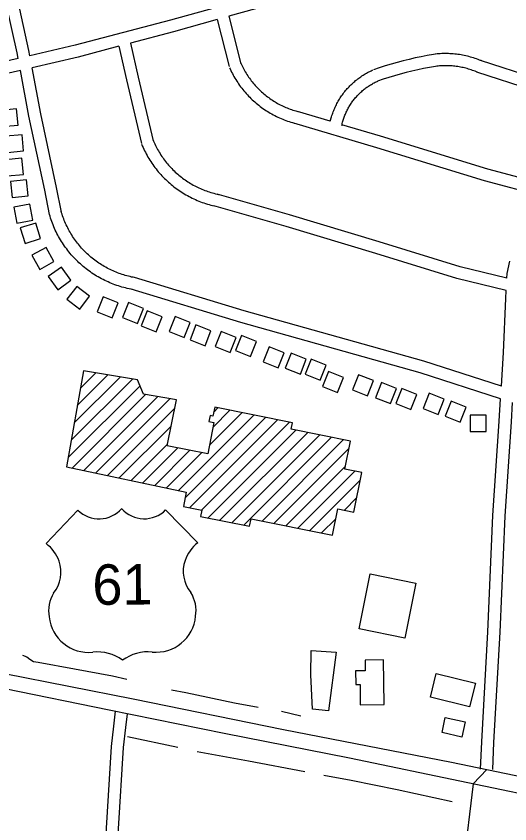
# Model space of a CAD drawing. Extents: x 3540316 to 3578335, y 553172 to 578787.
# Drawn here: x 3544439 to 3545660, y 572760 to 574758 of the extents above; entities that cross this region are included whole.
import ezdxf

# ---------------------------------------------------------------- set-up
doc = ezdxf.new("R2010")
doc.units = 0
for name, color, linetype in [('V-BLDG-OTLN', 7, 'Continuous'), ('V-ROAD-CNTR', 7, 'Continuous'), ('V-ROAD-IDEN', 7, 'Continuous'), ('V-TOPO-SHOR', 7, 'Continuous')]:
    doc.layers.add(name, color=color, linetype=linetype)

msp = doc.modelspace()

# ---------------------------------------------------------------- linework, layer by layer
at = {"layer": 'V-BLDG-OTLN'}
for p, q in [((3544583, 573752), (3544696.6, 573865.7)), ((3544590.5, 573794.9), (3544666.2, 573870.7)), ((3544598, 573837.8), (3544635.9, 573875.7)), ((3544567.9, 573666.3), (3544745.6, 573844)), ((3544575.5, 573709.2), (3544726.9, 573860.7)), ((3544577.5, 573640.5), (3544759.3, 573822.3)), ((3544606.7, 573634.4), (3544789.7, 573817.3)), ((3544636, 573628.3), (3544820, 573812.3)), ((3544665.2, 573622.1), (3544831.9, 573788.8)), ((3544926.2, 573741.7), (3544967.9, 573783.4)), ((3544927.8, 573778.7), (3544938.4, 573789.3)), ((3544840.5, 573585.3), (3545026.8, 573771.6)), ((3544857.1, 573566.6), (3545056.2, 573765.7)), ((3544917.3, 573697.5), (3544997.3, 573777.5)), ((3544918.9, 573769.8), (3544919.2, 573770.1)), ((3544694.4, 573616), (3544822.5, 573744.1)), ((3544868.5, 573542.6), (3545085.7, 573759.8)), ((3544898, 573536.7), (3545115.1, 573753.9)), ((3544913.8, 573517.2), (3545131.2, 573734.5)), ((3544943.3, 573511.3), (3545160.6, 573728.6)), ((3544972.7, 573505.4), (3545190.1, 573722.7)), ((3545002.2, 573499.5), (3545219.5, 573716.8)), ((3545047.5, 573509.4), (3545249, 573710.9)), ((3544723.6, 573609.9), (3544813.2, 573699.4)), ((3544752.9, 573603.7), (3544839.5, 573690.4)), ((3544782.1, 573597.6), (3544869, 573684.5)), ((3545076.9, 573503.5), (3545262.7, 573689.3)), ((3544811.3, 573591.5), (3544898.4, 573678.6)), ((3545106.4, 573497.6), (3545253.8, 573645.1)), ((3545135.8, 573491.7), (3545276.9, 573632.8)), ((3545165.3, 573485.8), (3545290.1, 573610.7)), ((3545251.2, 573536.4), (3545281.3, 573566.5)), ((3545194.7, 573479.9), (3545229.6, 573514.8))]:
    msp.add_line(p, q, dxfattribs=at)
for points in [[(3544404.1, 574485), (3544443.9, 574489), (3544440, 574528.8), (3544400.2, 574524.8)], [(3544418, 574421.4), (3544457.8, 574425.3), (3544453.8, 574465.1), (3544414, 574461.2)], [(3544417.3, 574363), (3544457.1, 574366.9), (3544453.1, 574406.7), (3544413.3, 574402.8)], [(3544429, 574309.9), (3544468.8, 574313.9), (3544464.9, 574353.7), (3544425.1, 574349.7)], [(3544480.6, 574253.6), (3544473.2, 574292.9), (3544433.9, 574285.6), (3544441.3, 574246.3)], [(3544499.5, 574208), (3544487.7, 574246.2), (3544449.5, 574234.4), (3544461.3, 574196.2)], [(3544532.5, 574151.3), (3544513.2, 574186.3), (3544478.2, 574167), (3544497.5, 574132)], [(3544574.5, 574105.1), (3544551.1, 574137.5), (3544518.7, 574114.1), (3544542.1, 574081.7)], [(3544620.9, 574065.4), (3544589.2, 574089.8), (3544564.8, 574058.1), (3544596.5, 574033.7)], [(3544691.5, 574049.6), (3544654.4, 574064.3), (3544639.6, 574027.2), (3544676.8, 574012.4)], [(3544753.9, 574035.1), (3544716.8, 574049.9), (3544702, 574012.7), (3544739.2, 573997.9)], [(3544800.5, 574014.7), (3544763.3, 574029.5), (3544748.5, 573992.3), (3544785.7, 573977.5)], [(3544869.8, 574000.4), (3544832.6, 574015.1), (3544817.9, 573978), (3544855, 573963.2)], [(3544921.1, 573980.3), (3544884, 573995.1), (3544869.2, 573957.9), (3544906.4, 573943.2)], [(3544983.3, 573963.4), (3544946.1, 573978.2), (3544931.4, 573941), (3544968.5, 573926.3)], [(3545033.6, 573953.3), (3544996.5, 573968), (3544981.7, 573930.9), (3545018.9, 573916.1)], [(3545101.9, 573925.3), (3545064.7, 573940.1), (3545050, 573902.9), (3545087.1, 573888.1)], [(3545156.9, 573909.6), (3545119.7, 573924.4), (3545104.9, 573887.2), (3545142.1, 573872.4)], [(3545206, 573895.1), (3545168.8, 573909.9), (3545154, 573872.7), (3545191.2, 573858)], [(3544605.5, 573880.7), (3544563.9, 573643.4), (3544860.1, 573581.2), (3544852.9, 573545.8), (3544898.4, 573536.7), (3544895.3, 573520.9), (3545016.6, 573496.6), (3545020.3, 573514.9), (3545221.5, 573474.5), (3545234.6, 573539.7), (3545274.3, 573531.8), (3545293.9, 573629.4), (3545252.4, 573637.8), (3545266.3, 573707.4), (3545119.3, 573736.9), (3545122.4, 573752.4), (3544930.3, 573790.9), (3544925.8, 573768.8), (3544919, 573770.2), (3544916.1, 573756), (3544928.5, 573753.5), (3544912.9, 573675.7), (3544812.4, 573695.8), (3544836.2, 573809.6), (3544754.4, 573823.1), (3544739.5, 573858.6)], [(3545249, 573864.3), (3545211.8, 573879), (3545197, 573841.9), (3545234.2, 573827.1)], [(3545323, 573856.7), (3545285.8, 573871.5), (3545271, 573834.3), (3545308.2, 573819.5)], [(3545379.9, 573837), (3545342.7, 573851.8), (3545327.9, 573814.6), (3545365.1, 573799.9)], [(3545430, 573822.8), (3545392.8, 573837.6), (3545378.1, 573800.4), (3545415.2, 573785.7)], [(3545498, 573810.6), (3545460.8, 573825.4), (3545446, 573788.2), (3545483.2, 573773.4)], [(3545552.2, 573791.4), (3545515, 573806.2), (3545500.3, 573769), (3545537.4, 573754.3)], [(3545601.7, 573731.2), (3545601.8, 573771.2), (3545561.8, 573771.3), (3545561.7, 573731.3)], [(3545287.7, 573242.5), (3545315.1, 573378.5), (3545427.5, 573355.9), (3545400.1, 573219.9)], [(3545168.8, 573189.5), (3545230.5, 573184.9), (3545212.1, 573040), (3545172.3, 573044.3), (3545167.9, 573128.7)], [(3545349.1, 573055.5), (3545347.7, 573166.1), (3545302.1, 573165.6), (3545302.4, 573139.1), (3545278.6, 573138.8), (3545279.1, 573104.8), (3545289.7, 573104.9), (3545290.3, 573054.8)], [(3545560.6, 573049.6), (3545463.6, 573073.6), (3545478.1, 573132.2), (3545575.1, 573108.3)], [(3545500.6, 573023.1), (3545549.6, 573012.4), (3545541.5, 572975.2), (3545492.5, 572986)]]:
    msp.add_lwpolyline(points, close=True, dxfattribs=at)
at = {"layer": 'V-ROAD-CNTR'}
for points in [[(3545484, 574933.3), (3545477.5, 574932.4), (3545359.8, 574896.4), (3545089.5, 574823.6), (3544820.7, 574748.7), (3544585.6, 574686.2), (3544473.3, 574660.3)], [(3546027.4, 574746.2), (3545911.1, 574783.8), (3545662.4, 574859.3), (3545540.2, 574894.9), (3545502.6, 574905.8), (3545484.1, 574903), (3545368.1, 574867.6), (3545097.4, 574794.7), (3544965.5, 574757.9)], [(3544473.3, 574660.3), (3544470.9, 574673.5), (3544444.2, 574794.2), (3544419.1, 574861.9), (3544397.2, 574897.7)], [(3544444.1, 574653.5), (3544441.5, 574667.5), (3544415.3, 574785.7), (3544392, 574848.8), (3544385.4, 574859.6)], [(3544936.6, 574749.8), (3544828.6, 574719.7), (3544722.1, 574691.4)], [(3544936.6, 574749.8), (3544965.9, 574633.4)], [(3544965.5, 574757.9), (3544995, 574640.7)], [(3544693.1, 574683.7), (3544592.8, 574657.1), (3544478.9, 574630.8)], [(3544693.1, 574683.7), (3544712.1, 574600.6), (3544748.9, 574443.5)], [(3544722.1, 574691.4), (3544741.4, 574607.4), (3544778.1, 574450.3)], [(3545475.5, 574664.2), (3545471.1, 574663.5), (3545456, 574660.9), (3545441, 574658.1), (3545426, 574654.9), (3545411, 574651.5), (3545396.2, 574647.8), (3545381.3, 574643.9), (3545366.5, 574639.7), (3545351.9, 574635.3), (3545337.3, 574630.6), (3545322.9, 574625.7)], [(3545590.7, 574647.5), (3545589, 574648.3), (3545585.3, 574649.8), (3545581.6, 574651.2), (3545577.9, 574652.5), (3545574.2, 574653.8), (3545570.4, 574655.1), (3545566.6, 574656.2), (3545562.8, 574657.3), (3545559, 574658.4), (3545555.1, 574659.3), (3545551.3, 574660.2), (3545547.4, 574661.1), (3545543.5, 574661.8), (3545539.6, 574662.5), (3545535.7, 574663.2), (3545531.8, 574663.7), (3545527.9, 574664.2), (3545523.9, 574664.6), (3545520, 574665), (3545516.1, 574665.3), (3545512.1, 574665.5), (3545508.2, 574665.6), (3545504.2, 574665.7), (3545500.2, 574665.7), (3545496.3, 574665.7), (3545492.3, 574665.6), (3545488.3, 574665.3), (3545484.4, 574665.1), (3545480.5, 574664.8), (3545476.6, 574664.3)], [(3544444.1, 574653.5), (3544396.5, 574642.6)], [(3544994.1, 574643.3), (3544995.4, 574640.3), (3544997, 574636.9), (3544998.7, 574633.5), (3545000.4, 574630.2), (3545002.2, 574626.9), (3545004.1, 574623.6), (3545006, 574620.3), (3545007.9, 574617.1), (3545009.9, 574614), (3545012, 574610.8), (3545014.1, 574607.7), (3545016.3, 574604.6), (3545018.5, 574601.6), (3545020.8, 574598.6), (3545023.2, 574595.7), (3545025.5, 574592.8), (3545027.9, 574589.9), (3545030.5, 574587.1), (3545033, 574584.3), (3545035.5, 574581.6), (3545038.2, 574578.9), (3545040.9, 574576.2), (3545043.6, 574573.6), (3545046.3, 574571.1), (3545049.1, 574568.6), (3545052, 574566.1), (3545054.9, 574563.7), (3545057.8, 574561.4), (3545060.8, 574559.1), (3545063.8, 574556.9), (3545066.9, 574554.7), (3545070, 574552.5), (3545073.1, 574550.4), (3545076.3, 574548.4), (3545079.5, 574546.4), (3545082.7, 574544.5), (3545086, 574542.6), (3545089.3, 574540.8), (3545092.6, 574539.1), (3545096, 574537.4), (3545099.4, 574535.8), (3545102.8, 574534.2), (3545106.2, 574532.7), (3545109.7, 574531.3), (3545113.2, 574529.9), (3545116.7, 574528.5), (3545120.2, 574527.3), (3545123.8, 574526.1), (3545127.4, 574524.9), (3545131, 574523.9), (3545134.7, 574522.8)], [(3545586.8, 574649.1), (3545724.2, 574604.9), (3545904, 574554.4)], [(3544449.6, 574624), (3544403.3, 574613.3)], [(3544521.7, 574267.5), (3544509.8, 574328.2), (3544470.7, 574511.2), (3544449.6, 574624)], [(3544551.1, 574273.3), (3544539.2, 574334.2), (3544500.1, 574517.1), (3544478.9, 574630.8)], [(3544966.8, 574630.8), (3544968.2, 574627.7), (3544970, 574623.8), (3544971.9, 574620), (3544973.9, 574616.2), (3544976, 574612.4), (3544978, 574608.7), (3544980.2, 574605), (3544982.4, 574601.3), (3544984.7, 574597.7), (3544987.1, 574594.1), (3544989.5, 574590.6), (3544992, 574587.1), (3544994.5, 574583.6), (3544997.1, 574580.2), (3544999.7, 574576.9), (3545002.5, 574573.5), (3545005.3, 574570.3), (3545008.1, 574567.1), (3545011, 574563.9), (3545013.9, 574560.8), (3545016.9, 574557.7), (3545019.9, 574554.7), (3545023, 574551.7), (3545026.2, 574548.8), (3545029.4, 574546), (3545032.7, 574543.2), (3545036, 574540.5), (3545039.3, 574537.8), (3545042.7, 574535.2), (3545046.1, 574532.6), (3545049.6, 574530.1), (3545053.1, 574527.7), (3545056.7, 574525.3), (3545060.3, 574523), (3545064, 574520.7), (3545067.7, 574518.6), (3545071.3, 574516.5), (3545075.1, 574514.4), (3545078.9, 574512.4), (3545082.8, 574510.5), (3545086.6, 574508.6), (3545090.5, 574506.9), (3545094.4, 574505.1), (3545098.4, 574503.5), (3545102.4, 574501.9), (3545106.3, 574500.4), (3545110.4, 574498.9), (3545114.5, 574497.6), (3545118.5, 574496.3), (3545122.6, 574495), (3545126.7, 574493.9)], [(3545216.1, 574498.4), (3545219.3, 574509.4), (3545220.3, 574512.5), (3545221.3, 574515.5), (3545222.3, 574518.6), (3545223.4, 574521.6), (3545224.6, 574524.6), (3545225.8, 574527.6), (3545227, 574530.5), (3545228.4, 574533.5), (3545229.7, 574536.4), (3545231.2, 574539.3), (3545232.6, 574542.1), (3545234.1, 574544.9), (3545235.7, 574547.8), (3545237.3, 574550.5), (3545239, 574553.3), (3545240.7, 574556), (3545242.4, 574558.7), (3545244.2, 574561.3), (3545246.1, 574564), (3545248, 574566.6), (3545249.9, 574569.1), (3545251.9, 574571.6), (3545253.9, 574574.1), (3545256, 574576.6), (3545258.1, 574579), (3545260.3, 574581.4), (3545262.5, 574583.8), (3545264.7, 574586), (3545267, 574588.3), (3545269.3, 574590.5), (3545271.7, 574592.7), (3545274.1, 574594.9), (3545276.5, 574596.9), (3545278.9, 574599), (3545281.5, 574601), (3545284, 574603), (3545286.6, 574604.9), (3545289.2, 574606.8), (3545291.8, 574608.6), (3545294.5, 574610.4), (3545297.2, 574612.2), (3545299.9, 574613.9), (3545302.7, 574615.5), (3545305.5, 574617.1), (3545308.2, 574618.6), (3545311.1, 574620.2), (3545314, 574621.6), (3545316.9, 574623), (3545319.8, 574624.4), (3545321.7, 574625.2)], [(3545480.3, 574634.6), (3545476.1, 574633.9), (3545461.4, 574631.4), (3545446.9, 574628.6), (3545432.4, 574625.6), (3545417.9, 574622.3), (3545403.6, 574618.8), (3545389.3, 574615), (3545375, 574610.9), (3545360.8, 574606.6), (3545346.8, 574602.2), (3545332.7, 574597.3)], [(3545579.1, 574619.9), (3545577.4, 574620.6), (3545574.2, 574621.9), (3545571.1, 574623.1), (3545567.8, 574624.3), (3545564.6, 574625.4), (3545561.3, 574626.5), (3545558, 574627.5), (3545554.7, 574628.5), (3545551.4, 574629.3), (3545548.1, 574630.2), (3545544.7, 574631), (3545541.4, 574631.7), (3545538, 574632.3), (3545534.6, 574633), (3545531.2, 574633.5), (3545527.8, 574634), (3545524.4, 574634.4), (3545521, 574634.8), (3545517.6, 574635.1), (3545514.1, 574635.3), (3545510.7, 574635.5), (3545507.3, 574635.7), (3545503.9, 574635.7), (3545500.4, 574635.7), (3545497, 574635.7), (3545493.6, 574635.6), (3545490.1, 574635.4), (3545486.6, 574635.2), (3545483.3, 574634.9), (3545479.8, 574634.5)], [(3545577.7, 574620.5), (3545715.5, 574576.2), (3545886.8, 574528.1)], [(3545245.1, 574489.7), (3545244.8, 574487.8), (3545245.3, 574490.4), (3545245.9, 574493.1), (3545246.6, 574495.7), (3545247.3, 574498.2), (3545248, 574500.8), (3545248.8, 574503.4), (3545249.7, 574506), (3545250.6, 574508.5), (3545251.5, 574511), (3545252.5, 574513.5), (3545253.5, 574516), (3545254.5, 574518.5), (3545255.6, 574520.9), (3545256.8, 574523.4), (3545258, 574525.8), (3545259.2, 574528.2), (3545260.5, 574530.6), (3545261.8, 574532.9), (3545263.1, 574535.2), (3545264.5, 574537.5), (3545265.9, 574539.8), (3545267.4, 574542.1), (3545268.9, 574544.3), (3545270.5, 574546.5), (3545272, 574548.6), (3545273.7, 574550.8), (3545275.4, 574552.9), (3545277, 574555), (3545278.8, 574557), (3545280.6, 574559.1), (3545282.4, 574561.1), (3545284.2, 574563), (3545286.1, 574564.9), (3545288, 574566.9), (3545289.9, 574568.7), (3545291.9, 574570.5), (3545293.9, 574572.3), (3545295.9, 574574.1), (3545298, 574575.8), (3545300.1, 574577.5), (3545302.2, 574579.1), (3545304.4, 574580.8), (3545306.5, 574582.3), (3545308.7, 574583.9), (3545311, 574585.4), (3545313.2, 574586.8), (3545315.5, 574588.3), (3545317.8, 574589.6), (3545320.2, 574590.9), (3545322.6, 574592.3), (3545324.9, 574593.5), (3545327.3, 574594.7), (3545329.7, 574595.9), (3545332.2, 574597), (3545333.8, 574597.8)], [(3545216.1, 574498.4), (3545135, 574522.7)], [(3545740.4, 574313.3), (3545597.6, 574351.2), (3545331.5, 574432.5), (3545126.4, 574494)], [(3545757.8, 574339.7), (3545605.8, 574380), (3545340.2, 574461.3), (3545245.1, 574489.7)], [(3544749.5, 574441.7), (3544751.2, 574437.7), (3544753, 574433.6), (3544754.8, 574429.6), (3544756.8, 574425.5), (3544758.8, 574421.5), (3544760.8, 574417.6), (3544763, 574413.7), (3544765.2, 574409.8), (3544767.5, 574406), (3544769.8, 574402.2), (3544772.2, 574398.5), (3544774.6, 574394.7), (3544777.2, 574391), (3544779.8, 574387.4), (3544782.5, 574383.9), (3544785.2, 574380.3), (3544788, 574376.8), (3544790.8, 574373.4), (3544793.8, 574370), (3544796.7, 574366.7), (3544799.7, 574363.4), (3544802.8, 574360.2), (3544805.9, 574357), (3544809.1, 574353.9), (3544812.4, 574350.8), (3544815.7, 574347.8), (3544819, 574344.9), (3544822.4, 574342), (3544825.9, 574339.1), (3544829.4, 574336.4), (3544832.9, 574333.7), (3544836.5, 574331), (3544840.2, 574328.5), (3544843.8, 574326), (3544847.5, 574323.5), (3544851.4, 574321.1), (3544855.1, 574318.8), (3544859, 574316.6), (3544862.9, 574314.4), (3544866.8, 574312.2), (3544870.8, 574310.2), (3544874.8, 574308.2), (3544878.8, 574306.3), (3544882.9, 574304.5), (3544886.9, 574302.7), (3544891, 574301), (3544895.3, 574299.4), (3544899.4, 574297.8), (3544903.6, 574296.4), (3544907.8, 574295), (3544912.1, 574293.6), (3544916.4, 574292.4), (3544920.7, 574291.2), (3544925, 574290.1), (3544929.4, 574289), (3544933.6, 574288.1), (3544934, 574288)], [(3544777.2, 574453.2), (3544778.8, 574449.5), (3544780.3, 574445.9), (3544782, 574442.3), (3544783.7, 574438.7), (3544785.4, 574435.3), (3544787.3, 574431.8), (3544789.2, 574428.3), (3544791.1, 574424.9), (3544793.1, 574421.5), (3544795.2, 574418.2), (3544797.3, 574414.8), (3544799.5, 574411.5), (3544801.7, 574408.3), (3544804, 574405.2), (3544806.4, 574402), (3544808.8, 574398.8), (3544811.3, 574395.8), (3544813.7, 574392.8), (3544816.3, 574389.8), (3544819, 574386.8), (3544821.6, 574383.9), (3544824.3, 574381.1), (3544827.1, 574378.3), (3544829.9, 574375.5), (3544832.8, 574372.8), (3544835.7, 574370.2), (3544838.7, 574367.6), (3544841.6, 574365), (3544844.7, 574362.6), (3544847.8, 574360.1), (3544850.9, 574357.7), (3544854.1, 574355.4), (3544857.3, 574353.1), (3544860.6, 574350.9), (3544863.8, 574348.7), (3544867.1, 574346.6), (3544870.5, 574344.6), (3544873.9, 574342.5), (3544877.3, 574340.6), (3544880.8, 574338.8), (3544884.3, 574337), (3544887.8, 574335.2), (3544891.4, 574333.5), (3544895, 574331.9), (3544898.6, 574330.4), (3544902.2, 574328.9), (3544905.9, 574327.4), (3544909.6, 574326.1), (3544913.3, 574324.7), (3544917, 574323.5), (3544920.8, 574322.3), (3544924.5, 574321.2), (3544928.4, 574320.2), (3544932.2, 574319.2), (3544936, 574318.3), (3544940, 574317.4), (3544940.5, 574317.3)], [(3545652.8, 574109.9), (3545537, 574138.2), (3545337.2, 574199.9), (3545115.3, 574266.7), (3544936.7, 574318.1)], [(3545651, 574079.5), (3545529, 574109.3), (3545328.5, 574171.2), (3545106.8, 574237.9), (3544928.4, 574289.3)], [(3544726.7, 574082.2), (3544723.1, 574082.9), (3544718.6, 574083.8), (3544714.1, 574084.8), (3544709.8, 574085.9), (3544705.4, 574087), (3544700.9, 574088.2), (3544696.5, 574089.5), (3544692.2, 574090.9), (3544687.9, 574092.4), (3544683.5, 574093.9), (3544679.3, 574095.5), (3544675.1, 574097.2), (3544670.8, 574098.9), (3544666.6, 574100.8), (3544662.5, 574102.7), (3544658.4, 574104.6), (3544654.3, 574106.6), (3544650.2, 574108.8), (3544646.2, 574110.9), (3544642.3, 574113.2), (3544638.3, 574115.5), (3544634.4, 574117.9), (3544630.6, 574120.3), (3544626.8, 574122.9), (3544623, 574125.5), (3544619.3, 574128.1), (3544615.6, 574130.9), (3544612.1, 574133.6), (3544608.4, 574136.5), (3544604.9, 574139.4), (3544601.5, 574142.3), (3544598, 574145.4), (3544594.6, 574148.5), (3544591.4, 574151.6), (3544588.1, 574154.8), (3544584.9, 574158.1), (3544581.8, 574161.4), (3544578.7, 574164.7), (3544575.7, 574168.2), (3544572.7, 574171.6), (3544569.8, 574175.2), (3544567, 574178.7), (3544564.2, 574182.4), (3544561.5, 574186.1), (3544558.8, 574189.7), (3544556.2, 574193.5), (3544553.7, 574197.3), (3544551.3, 574201.2), (3544548.9, 574205.1), (3544546.6, 574209), (3544544.3, 574213), (3544542.1, 574217), (3544540.1, 574221.1), (3544538, 574225.1), (3544536.1, 574229.3), (3544534.2, 574233.4), (3544532.3, 574237.6), (3544530.6, 574241.9), (3544529, 574246), (3544527.3, 574250.4), (3544525.8, 574254.7), (3544524.4, 574259), (3544523, 574263.3), (3544521.7, 574267.6)], [(3544732.2, 574111.7), (3544728.8, 574112.4), (3544724.9, 574113.1), (3544721, 574114), (3544717, 574115), (3544713.1, 574116), (3544709.2, 574117.1), (3544705.4, 574118.2), (3544701.5, 574119.5), (3544697.6, 574120.7), (3544693.9, 574122.1), (3544690.1, 574123.5), (3544686.3, 574125), (3544682.6, 574126.5), (3544678.9, 574128.2), (3544675.2, 574129.8), (3544671.5, 574131.6), (3544667.9, 574133.4), (3544664.3, 574135.2), (3544660.8, 574137.2), (3544657.3, 574139.2), (3544653.8, 574141.2), (3544650.4, 574143.3), (3544646.9, 574145.5), (3544643.6, 574147.7), (3544640.2, 574150), (3544637, 574152.4), (3544633.7, 574154.8), (3544630.5, 574157.3), (3544627.3, 574159.8), (3544624.3, 574162.3), (3544621.1, 574165), (3544618.1, 574167.7), (3544615.2, 574170.4), (3544612.2, 574173.2), (3544609.3, 574176), (3544606.5, 574178.9), (3544603.7, 574181.8), (3544601, 574184.8), (3544598.3, 574187.8), (3544595.7, 574190.9), (3544593.1, 574194), (3544590.6, 574197.2), (3544588.2, 574200.4), (3544585.8, 574203.6), (3544583.4, 574207), (3544581.1, 574210.3), (3544578.9, 574213.6), (3544576.7, 574217.1), (3544574.6, 574220.5), (3544572.6, 574224), (3544570.6, 574227.5), (3544568.7, 574231), (3544566.8, 574234.6), (3544565, 574238.3), (3544563.2, 574241.9), (3544561.6, 574245.6), (3544560, 574249.3), (3544558.4, 574253), (3544556.9, 574256.8), (3544555.5, 574260.6), (3544554.2, 574264.4), (3544552.9, 574268.3), (3544551.7, 574272.1), (3544550.5, 574276)], [(3545652.8, 574109.9), (3545653.6, 574122.1), (3545660.2, 574152.4)], [(3545639.4, 573842.8), (3545447.3, 573904.6), (3545003.2, 574029.3), (3544732.2, 574111.6)], [(3545637.5, 573811.9), (3545438.7, 573875.9), (3544994.8, 574000.5), (3544723.5, 574082.9)], [(3545639.4, 573842.8), (3545644.6, 573926.5), (3545649.9, 574060.2), (3545651, 574079.5)], [(3545587.9, 572895.6), (3545590.6, 572963.3), (3545605.9, 573235.8), (3545618.5, 573523), (3545634.1, 573756.7), (3545637.5, 573811.9)], [(3545617.9, 572894.5), (3545620.5, 572961.8), (3545635.9, 573234.3), (3545648.5, 573521.3), (3545664.1, 573754.8), (3545667, 573802.4)], [(3544410.8, 573132.1), (3544728.4, 573069.5), (3545100.5, 572993.8), (3545515.6, 572913.3), (3545869.3, 572839.3), (3546224.2, 572767), (3546505.2, 572702.3)], [(3546286.1, 572713.1), (3545996.1, 572774.7), (3545786.3, 572813.7), (3545556.4, 572862.1), (3545264, 572922.9), (3544953.3, 572984.2), (3544669.5, 573041.9), (3544411.1, 573094.2)], [(3544651.9, 572546.9), (3544662.5, 572749.7), (3544675.2, 572951.6), (3544681, 573002.4), (3544684.8, 573038.8)], [(3544681.8, 572545.3), (3544692.4, 572748), (3544705.1, 572948.9), (3544710.8, 572999.1), (3544714.4, 573032.8)], [(3545602.9, 572895.1), (3545569.5, 572859.2)], [(3545569.5, 572859.2), (3545545.7, 572661.4), (3545516.3, 572306.5), (3545485.7, 571686.4)]]:
    msp.add_lwpolyline(points, dxfattribs=at)
at = {"layer": 'V-ROAD-IDEN'}
for p, q in [((3544513.4, 573453.7), (3544591.9, 573536)), ((3544888.4, 573455.4), (3544809, 573536.9))]:
    msp.add_line(p, q, dxfattribs=at)
for centre, major_axis, start_param, end_param in [((3544644.2, 573589.8), (0.6, -75), 5.502702, 7.121811), ((3544756.1, 573590), (-0.6, 75), 2.291842, 3.917604), ((3544458.7, 573379.5), (-0.7, 92.2), 5.045266, 5.638568), ((3544943.9, 573381.9), (0.7, -92.2), 3.781672, 4.374974), ((3544468.8, 573382.7), (-0.6, 81.6), 4.021008, 5.049788), ((3544933.8, 573385), (0.6, -81.6), 4.370452, 5.399232), ((3544605.9, 573286.6), (0.7, -86.5), 4.163028, 4.868958), ((3544797.8, 573287.3), (-0.7, 86.5), 4.551282, 5.257212), ((3544618.8, 573283.3), (-0.8, 98.8), 1.672766, 3.238327), ((3544785, 573283.8), (0.8, -98.8), 6.181885, 7.747479), ((3544640.6, 573080), (-0.8, 105.6), 5.646836, 6.385311), ((3544765.4, 573080.3), (0.8, -105.6), 3.034929, 3.773404)]:
    msp.add_ellipse(centre, major_axis=major_axis, ratio=0.99789, start_param=start_param, end_param=end_param, dxfattribs=at)
at = {"layer": 'V-TOPO-SHOR'}
for p, q in [((3545095.1, 573039.4), (3545143.5, 573027.4)), ((3544714.7, 572976.8), (3544839.2, 572949.9))]:
    msp.add_line(p, q, dxfattribs=at)
for points in [[(3544455.3, 573178), (3544465.7, 573173.8), (3544473.3, 573167.6), (3544482.2, 573162), (3544493.3, 573160.6), (3544583.9, 573143.5), (3544677.3, 573126.5), (3544712.6, 573118.7)], [(3544823.2, 573091.9), (3544858.5, 573085.5), (3544979.5, 573060), (3545037.7, 573048.7)], [(3544886.9, 572939.3), (3545013.5, 572915.9), (3545153.2, 572889.6)], [(3545200.3, 572881.1), (3545268.1, 572868.3), (3545381.5, 572845.7), (3545517.8, 572816)]]:
    msp.add_lwpolyline(points, dxfattribs=at)

# ---------------------------------------------------------------- texts
at = {"layer": 'V-ROAD-IDEN'}
msp.add_text('61', height=100, rotation=0.4506, dxfattribs=at).set_placement((3544628.1, 573302))

doc.saveas('drawing.dxf')
